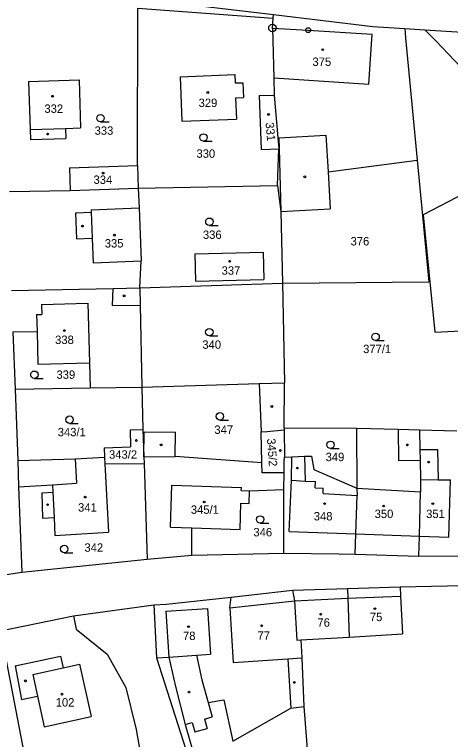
# Model space of a CAD drawing. Extents: x -779596 to -776743, y -1030330 to -1024513.
# Drawn here: x -778185.6 to -778097.2, y -1024857.5 to -1024710.7 of the extents above; entities that cross this region are included whole.
import ezdxf

# ---------------------------------------------------------------- set-up
doc = ezdxf.new("R2010")
doc.units = 0
for name, color, linetype in [('hranice parcel', 7, 'Continuous'), ('hranice vnitřní', 7, 'Continuous'), ('kultura', 7, 'Continuous'), ('Kód', 7, 'Continuous'), ('č_pacel stav_', 7, 'Continuous'), ('č_parcel poz_', 7, 'Continuous')]:
    doc.layers.add(name, color=color, linetype=linetype)

msp = doc.modelspace()

# ---------------------------------------------------------------- linework, layer by layer
at = {"layer": 'hranice parcel'}
for points in [[(-778160.55, -1024707.39), (-778133.07, -1024710.69)], [(-778160.63, -1024741.23), (-778160.55, -1024709.39)], [(-778160.55, -1024709.39), (-778133.13, -1024711.38)], [(-778133.13, -1024711.38), (-778133.07, -1024710.69)], [(-778133.07, -1024710.69), (-778112.97, -1024713.11)], [(-778133.3, -1024713.41), (-778133.13, -1024711.38)], [(-778133.3, -1024713.41), (-778133.03, -1024723.5)], [(-778112.97, -1024713.11), (-778106.49, -1024713.51)], [(-778106.49, -1024713.51), (-778106.32, -1024715.36)], [(-778106.49, -1024713.51), (-778102.38, -1024713.77)], [(-778102.38, -1024713.77), (-778087.35, -1024714.71)], [(-778102.38, -1024713.77), (-778100.2, -1024716.03)], [(-778106.32, -1024715.36), (-778103.98, -1024740.19)], [(-778100.2, -1024716.03), (-778095.04, -1024721.38)], [(-778151.98, -1024723.26), (-778140.93, -1024722.84)], [(-778140.93, -1024722.84), (-778140.87, -1024724.53)], [(-778182.73, -1024724.25), (-778172.49, -1024723.92)], [(-778182.73, -1024724.25), (-778182.41, -1024733.97)], [(-778172.49, -1024723.92), (-778172.17, -1024733.64)], [(-778151.98, -1024723.26), (-778151.64, -1024732.27)], [(-778133.03, -1024723.5), (-778132.93, -1024726.98)], [(-778140.87, -1024724.53), (-778139.26, -1024724.47)], [(-778139.26, -1024724.47), (-778139.15, -1024727.48)], [(-778135.96, -1024727.06), (-778132.93, -1024726.98)], [(-778135.96, -1024727.06), (-778135.57, -1024738)], [(-778132.93, -1024726.98), (-778132.21, -1024735.64)], [(-778140.76, -1024727.54), (-778139.15, -1024727.48)], [(-778140.76, -1024727.54), (-778140.6, -1024731.86)], [(-778151.64, -1024732.27), (-778140.6, -1024731.86)], [(-778182.41, -1024733.97), (-778182.34, -1024735.96)], [(-778175.24, -1024733.74), (-778172.17, -1024733.64)], [(-778175.24, -1024733.74), (-778175.17, -1024735.77)], [(-778182.34, -1024735.96), (-778175.17, -1024735.77)], [(-778132.21, -1024735.64), (-778132.02, -1024737.88)], [(-778135.57, -1024738), (-778132.02, -1024737.88)], [(-778132.26, -1024745.3), (-778132.02, -1024737.88)], [(-778122.03, -1024742.54), (-778103.98, -1024740.19)], [(-778103.98, -1024740.19), (-778101.62, -1024764.81)], [(-778174.43, -1024741.71), (-778160.63, -1024741.23)], [(-778174.43, -1024741.71), (-778174.27, -1024746.3)], [(-778160.63, -1024741.23), (-778160.47, -1024745.82)], [(-778082.6, -1024740.74), (-778102.73, -1024751.23)], [(-778122.03, -1024742.54), (-778121.59, -1024750.05)], [(-778186.58, -1024746.54), (-778174.27, -1024746.3)], [(-778174.27, -1024746.3), (-778160.47, -1024745.82)], [(-778160.47, -1024745.82), (-778132.26, -1024745.3)], [(-778160.47, -1024745.82), (-778160.29, -1024749.84)], [(-778132.26, -1024745.3), (-778131.57, -1024750.56)], [(-778160.29, -1024749.84), (-778159.87, -1024760.58)], [(-778131.57, -1024750.56), (-778121.59, -1024750.05)], [(-778131.57, -1024750.56), (-778131.28, -1024765.07)], [(-778102.73, -1024751.23), (-778100.38, -1024775)], [(-778149, -1024759.12), (-778135.14, -1024758.79)], [(-778149, -1024759.12), (-778148.87, -1024764.68)], [(-778135.14, -1024758.79), (-778135.01, -1024764.35)], [(-778160.16, -1024766.03), (-778159.87, -1024760.58)], [(-778160.16, -1024766.03), (-778131.28, -1024765.07)], [(-778148.87, -1024764.68), (-778135.01, -1024764.35)], [(-778131.28, -1024765.07), (-778101.62, -1024764.81)], [(-778131.28, -1024765.07), (-778130.87, -1024785.26)], [(-778186.2, -1024766.58), (-778165.58, -1024766.14)], [(-778165.58, -1024766.14), (-778160.16, -1024766.03)], [(-778160.16, -1024766.03), (-778160.09, -1024769.5)], [(-778160.09, -1024769.5), (-778159.76, -1024786.14)], [(-778100.38, -1024775), (-778068.42, -1024773.37)], [(-778185.87, -1024774.95), (-778180.98, -1024774.86)], [(-778185.87, -1024774.95), (-778185.42, -1024786.53)], [(-778180.98, -1024774.86), (-778180.8, -1024781.49)], [(-778180.8, -1024781.49), (-778170.38, -1024781.21)], [(-778170.38, -1024781.21), (-778170.24, -1024786.3)], [(-778159.76, -1024786.14), (-778135.98, -1024785.42)], [(-778135.98, -1024785.42), (-778130.87, -1024785.26)], [(-778135.98, -1024785.42), (-778135.58, -1024795.2)], [(-778130.92, -1024794.35), (-778130.87, -1024785.26)], [(-778185.42, -1024786.53), (-778170.24, -1024786.3)], [(-778185.42, -1024786.53), (-778184.91, -1024800.99)], [(-778170.24, -1024786.3), (-778159.76, -1024786.14)], [(-778159.76, -1024786.14), (-778159.57, -1024794.74)], [(-778162.14, -1024794.79), (-778159.57, -1024794.74)], [(-778162.14, -1024794.79), (-778162.06, -1024798.24)], [(-778159.57, -1024794.74), (-778159.33, -1024800.24)], [(-778130.92, -1024794.35), (-778130.92, -1024794.8)], [(-778130.92, -1024794.35), (-778116.26, -1024794.42)], [(-778116.26, -1024794.42), (-778116.17, -1024806.58)], [(-778116.26, -1024794.42), (-778107.83, -1024794.65)], [(-778107.83, -1024794.65), (-778103.48, -1024794.77)], [(-778103.48, -1024794.77), (-778103.42, -1024798.74)], [(-778103.48, -1024794.77), (-778095.94, -1024795)], [(-778159.33, -1024800.24), (-778159.29, -1024795.19)], [(-778159.29, -1024795.19), (-778152.93, -1024795.26)], [(-778152.99, -1024800.2), (-778152.93, -1024795.26)], [(-778135.43, -1024801.46), (-778135.58, -1024795.2)], [(-778130.92, -1024794.8), (-778130.86, -1024800.3)], [(-778167.41, -1024798.41), (-778162.06, -1024798.24)], [(-778167.41, -1024798.41), (-778167.3, -1024800.33)], [(-778103.42, -1024798.74), (-778103.38, -1024800.89)], [(-778184.91, -1024800.99), (-778173.3, -1024800.66)], [(-778173.3, -1024800.66), (-778167.3, -1024800.33)], [(-778167.3, -1024800.33), (-778167.23, -1024801.67)], [(-778159.33, -1024800.24), (-778159.28, -1024801.62)], [(-778135.43, -1024801.46), (-778152.99, -1024800.2)], [(-778130.95, -1024801.32), (-778130.86, -1024800.3)], [(-778130.86, -1024800.3), (-778129.35, -1024800.24)], [(-778129.35, -1024800.24), (-778126.82, -1024800.14)], [(-778126.82, -1024800.14), (-778125.37, -1024800.09)], [(-778125.37, -1024800.09), (-778124.91, -1024802.79)], [(-778184.91, -1024800.99), (-778184.72, -1024806.35)], [(-778167.23, -1024801.67), (-778159.28, -1024801.62)], [(-778167.23, -1024801.67), (-778166.49, -1024815.49)], [(-778159.28, -1024801.62), (-778158.66, -1024820.94)], [(-778135.38, -1024803.47), (-778135.43, -1024801.46)], [(-778130.95, -1024803.45), (-778130.95, -1024801.32)], [(-778103.38, -1024800.89), (-778103.32, -1024804.84)], [(-778130.95, -1024803.45), (-778135.38, -1024803.47)], [(-778130.96, -1024806.88), (-778130.95, -1024803.45)], [(-778124.91, -1024802.79), (-778116.17, -1024806.58)], [(-778103.32, -1024804.84), (-778103.28, -1024807.34)], [(-778184.72, -1024806.35), (-778177.86, -1024805.91)], [(-778184.72, -1024806.35), (-778184.1, -1024823.61)], [(-778177.86, -1024805.91), (-778177.79, -1024807.4)], [(-778180.01, -1024807.51), (-778177.79, -1024807.4)], [(-778180.01, -1024807.51), (-778179.86, -1024812.64)], [(-778138.03, -1024809.68), (-778137.93, -1024807.13)], [(-778137.93, -1024807.13), (-778130.96, -1024806.88)], [(-778130.98, -1024819.72), (-778130.96, -1024806.88)], [(-778116.17, -1024806.58), (-778116.13, -1024808.08)], [(-778103.52, -1024816.29), (-778103.28, -1024807.34)], [(-778116.41, -1024815.83), (-778116.13, -1024808.08)], [(-778139.86, -1024814.97), (-778139.69, -1024809.63)], [(-778139.69, -1024809.63), (-778138.03, -1024809.68)], [(-778179.86, -1024812.64), (-778177.54, -1024812.53)], [(-778177.54, -1024812.53), (-778177.37, -1024816.18)], [(-778149.66, -1024820.13), (-778149.61, -1024814.65)], [(-778149.61, -1024814.65), (-778139.86, -1024814.97)], [(-778177.37, -1024816.18), (-778166.49, -1024815.49)], [(-778116.51, -1024819.97), (-778116.41, -1024815.83)], [(-778103.61, -1024820.37), (-778103.52, -1024816.29)], [(-778149.66, -1024820.13), (-778130.98, -1024819.72)], [(-778130.98, -1024819.72), (-778119.86, -1024819.87)], [(-778184.1, -1024823.61), (-778158.66, -1024820.94)], [(-778158.66, -1024820.94), (-778149.66, -1024820.13)], [(-778119.86, -1024819.87), (-778116.51, -1024819.97)], [(-778116.51, -1024819.97), (-778103.61, -1024820.37)], [(-778103.61, -1024820.37), (-778090.93, -1024820.32)], [(-778193.9, -1024825.06), (-778184.1, -1024823.61)], [(-778129.21, -1024827.27), (-778118.06, -1024826.92)], [(-778118.06, -1024826.92), (-778107.44, -1024826.59)], [(-778118.06, -1024826.92), (-778118, -1024828.86)], [(-778107.44, -1024826.59), (-778091.45, -1024826.23)], [(-778107.44, -1024826.59), (-778107.34, -1024828.45)], [(-778141.64, -1024828.64), (-778129.21, -1024827.27)], [(-778129.21, -1024827.27), (-778128.79, -1024829.43)], [(-778107.34, -1024828.45), (-778106.94, -1024836.07)], [(-778154.81, -1024830.1), (-778141.64, -1024828.64)], [(-778141.94, -1024830.85), (-778141.64, -1024828.64)], [(-778128.79, -1024829.43), (-778128.38, -1024837.37)], [(-778118, -1024828.86), (-778117.77, -1024836.73)], [(-778173.59, -1024832.42), (-778157.31, -1024830.23)], [(-778157.31, -1024830.23), (-778154.81, -1024830.1)], [(-778157.31, -1024830.23), (-778156.76, -1024840.95)], [(-778141.94, -1024830.85), (-778141.22, -1024841.91)], [(-778188.42, -1024835.49), (-778173.59, -1024832.42)], [(-778173.59, -1024832.42), (-778173.06, -1024835.13)], [(-778173.06, -1024835.13), (-778166.78, -1024840.23)], [(-778128.38, -1024837.37), (-778127.54, -1024837.32)], [(-778127.54, -1024837.32), (-778117.77, -1024836.73)], [(-778127.54, -1024837.32), (-778127.37, -1024840.94)], [(-778117.77, -1024836.73), (-778106.94, -1024836.07)], [(-778187.93, -1024838.01), (-778180.36, -1024877.36)], [(-778166.78, -1024840.23), (-778163, -1024846.97)], [(-778185.41, -1024842.59), (-778176.25, -1024840.62)], [(-778176.25, -1024840.62), (-778175.73, -1024842.98)], [(-778156.76, -1024840.95), (-778154.27, -1024840.78)], [(-778156.76, -1024840.95), (-778150.3, -1024861.21)], [(-778154.27, -1024840.78), (-778152.92, -1024846.76)], [(-778141.22, -1024841.91), (-778130.18, -1024841.13)], [(-778130.18, -1024841.13), (-778127.37, -1024840.94)], [(-778127.37, -1024840.94), (-778126.92, -1024850.83)], [(-778185.41, -1024842.59), (-778184.15, -1024849.36)], [(-778175.73, -1024842.98), (-778172.36, -1024842.22)], [(-778172.36, -1024842.22), (-778170.04, -1024852.82)], [(-778163, -1024846.97), (-778160.91, -1024855.45)], [(-778152.92, -1024846.76), (-778150.99, -1024854.44)], [(-778184.15, -1024849.36), (-778180.91, -1024848.68)], [(-778180.91, -1024848.68), (-778179.55, -1024854.91)], [(-778146.31, -1024850.01), (-778143.11, -1024849.44)], [(-778146.31, -1024850.01), (-778145.5, -1024852.91)], [(-778143.11, -1024849.44), (-778141.34, -1024857.84)], [(-778141.34, -1024857.84), (-778129.56, -1024851.15)], [(-778129.56, -1024851.15), (-778126.92, -1024850.83)], [(-778126.92, -1024850.83), (-778125.81, -1024865.47)], [(-778179.55, -1024854.91), (-778170.04, -1024852.82)], [(-778147.06, -1024853.34), (-778145.5, -1024852.91)], [(-778147.06, -1024853.34), (-778146.53, -1024855.24)], [(-778150.99, -1024854.44), (-778149.54, -1024854.03)], [(-778150.99, -1024854.44), (-778145, -1024875.04)], [(-778149.54, -1024854.03), (-778149.01, -1024855.96)], [(-778160.91, -1024855.45), (-778157.79, -1024873.21)], [(-778149.01, -1024855.96), (-778146.53, -1024855.24)]]:
    msp.add_lwpolyline(points, dxfattribs=at)
at = {"layer": 'hranice vnitřní'}
for points in [[(-778133.3, -1024713.41), (-778126.07, -1024713.84)], [(-778126.07, -1024713.84), (-778113.07, -1024714.62)], [(-778113.77, -1024724.78), (-778113.07, -1024714.62)], [(-778133.03, -1024723.5), (-778113.77, -1024724.78)], [(-778182.41, -1024733.97), (-778175.24, -1024733.74)], [(-778132.21, -1024735.64), (-778132.01, -1024735.63)], [(-778132.01, -1024735.63), (-778122.46, -1024735.08)], [(-778132.01, -1024735.63), (-778131.94, -1024737.88)], [(-778122.46, -1024735.08), (-778122.03, -1024742.54)], [(-778131.94, -1024737.88), (-778131.57, -1024750.56)], [(-778173.2, -1024750.85), (-778170.02, -1024750.72)], [(-778170.04, -1024750.22), (-778160.29, -1024749.84)], [(-778170.04, -1024750.22), (-778170.02, -1024750.72)], [(-778170.02, -1024750.72), (-778169.81, -1024755.97)], [(-778173.2, -1024750.85), (-778173, -1024756.1)], [(-778173, -1024756.1), (-778169.81, -1024755.97)], [(-778169.81, -1024755.97), (-778169.61, -1024760.96)], [(-778169.61, -1024760.96), (-778159.87, -1024760.58)], [(-778165.72, -1024769.62), (-778165.58, -1024766.14)], [(-778180.09, -1024769.39), (-778170.71, -1024769.14)], [(-778180.09, -1024769.39), (-778180.03, -1024771.39)], [(-778170.71, -1024769.14), (-778170.38, -1024781.21)], [(-778165.72, -1024769.62), (-778160.09, -1024769.5)], [(-778181.08, -1024771.42), (-778180.03, -1024771.39)], [(-778181.08, -1024771.42), (-778180.98, -1024774.86)], [(-778107.83, -1024794.65), (-778107.73, -1024800.97)], [(-778135.58, -1024795.2), (-778134.38, -1024795.1)], [(-778134.38, -1024795.1), (-778130.92, -1024794.8)], [(-778103.42, -1024798.74), (-778099.87, -1024798.79)], [(-778099.87, -1024798.79), (-778099.71, -1024804.89)], [(-778173.3, -1024800.66), (-778173, -1024805.6)], [(-778159.33, -1024800.24), (-778152.99, -1024800.2)], [(-778129.44, -1024804.99), (-778129.35, -1024800.24)], [(-778126.82, -1024800.14), (-778126.63, -1024805.15)], [(-778107.73, -1024800.97), (-778103.38, -1024800.89)], [(-778129.92, -1024815.34), (-778129.44, -1024804.99)], [(-778129.44, -1024804.99), (-778126.63, -1024805.15)], [(-778103.32, -1024804.84), (-778099.71, -1024804.89)], [(-778099.71, -1024804.89), (-778097.24, -1024804.92)], [(-778097.52, -1024816.51), (-778097.24, -1024804.92)], [(-778177.86, -1024805.91), (-778173, -1024805.6)], [(-778153.96, -1024814.51), (-778153.68, -1024805.96)], [(-778153.68, -1024805.96), (-778139.58, -1024806.42)], [(-778139.61, -1024807.08), (-778139.58, -1024806.42)], [(-778126.63, -1024805.15), (-778124.57, -1024805.27)], [(-778124.64, -1024806.49), (-778124.57, -1024805.27)], [(-778124.64, -1024806.49), (-778122.98, -1024806.58)], [(-778177.79, -1024807.4), (-778177.54, -1024812.53)], [(-778139.61, -1024807.08), (-778137.93, -1024807.13)], [(-778123.04, -1024807.68), (-778122.98, -1024806.58)], [(-778123.04, -1024807.68), (-778116.13, -1024808.08)], [(-778116.17, -1024806.58), (-778103.28, -1024807.34)], [(-778153.96, -1024814.51), (-778149.61, -1024814.65)], [(-778129.92, -1024815.34), (-778116.41, -1024815.83)], [(-778116.41, -1024815.83), (-778103.52, -1024816.29)], [(-778103.52, -1024816.29), (-778097.52, -1024816.51)], [(-778118, -1024828.86), (-778107.34, -1024828.45)], [(-778141.94, -1024830.85), (-778128.79, -1024829.43)], [(-778128.79, -1024829.43), (-778118, -1024828.86)], [(-778154.89, -1024831.5), (-778146.45, -1024830.93)], [(-778146.45, -1024830.93), (-778145.83, -1024840.21)], [(-778154.89, -1024831.5), (-778154.27, -1024840.78)], [(-778148.68, -1024840.41), (-778145.83, -1024840.21)], [(-778154.27, -1024840.78), (-778148.68, -1024840.41)], [(-778148.68, -1024840.41), (-778147.6, -1024845.38)], [(-778130.18, -1024841.13), (-778129.56, -1024851.15)], [(-778181.87, -1024844.31), (-778175.73, -1024842.98)], [(-778181.87, -1024844.31), (-778180.91, -1024848.68)], [(-778147.6, -1024845.38), (-778146.31, -1024850.01)]]:
    msp.add_lwpolyline(points, dxfattribs=at)
at = {"layer": 'kultura'}
for points in [[(-778168.12, -1024732.4), (-778166.37, -1024732.4)], [(-778147.27, -1024736.31), (-778145.52, -1024736.31)], [(-778146.07, -1024753.38), (-778144.32, -1024753.38)], [(-778146.08, -1024775.75), (-778144.33, -1024775.75)], [(-778112.39, -1024776.69), (-778110.64, -1024776.69)], [(-778181.53, -1024784.36), (-778179.78, -1024784.36)], [(-778143.94, -1024792.79), (-778142.19, -1024792.79)], [(-778174.4, -1024793.47), (-778172.65, -1024793.47)], [(-778121.52, -1024798.55), (-778119.77, -1024798.55)], [(-778135.79, -1024813.67), (-778134.04, -1024813.67)], [(-778175.48, -1024819.66), (-778173.73, -1024819.66)]]:
    msp.add_lwpolyline(points, dxfattribs=at)
for centre, radius in [((-778123.11, -1024717.79), 0.175), ((-778177.86, -1024727.21), 0.175), ((-778146.4, -1024726.46), 0.175), ((-778168.12, -1024731.65), 0.75), ((-778134.07, -1024730.9), 0.175), ((-778178.84, -1024734.89), 0.175), ((-778147.27, -1024735.56), 0.75), ((-778167.58, -1024742.79), 0.175), ((-778126.75, -1024743.54), 0.175), ((-778146.07, -1024752.63), 0.75), ((-778171.8, -1024753.51), 0.175), ((-778165.31, -1024755.35), 0.175), ((-778141.96, -1024760.63), 0.175), ((-778163.36, -1024767.64), 0.175), ((-778175.47, -1024774.67), 0.175), ((-778146.08, -1024775), 0.75), ((-778112.39, -1024775.94), 0.75), ((-778181.53, -1024783.61), 0.75), ((-778133.4, -1024790.05), 0.175), ((-778143.94, -1024792.04), 0.75), ((-778174.4, -1024792.72), 0.75), ((-778160.87, -1024796.93), 0.175), ((-778155.84, -1024797.82), 0.175), ((-778121.52, -1024797.8), 0.75), ((-778105.95, -1024797.83), 0.175), ((-778131.69, -1024798.96), 0.175), ((-778101.63, -1024801.31), 0.175), ((-778128.24, -1024802.51), 0.175), ((-778171.26, -1024808.4), 0.175), ((-778147.12, -1024809.4), 0.175), ((-778178.84, -1024809.92), 0.175), ((-778122.72, -1024809.72), 0.175), ((-778110.75, -1024810.2), 0.175), ((-778100.79, -1024809.72), 0.175), ((-778135.79, -1024812.92), 0.75), ((-778175.48, -1024818.91), 0.75), ((-778112.53, -1024830.98), 0.175), ((-778123.53, -1024832.11), 0.175), ((-778135.48, -1024834.46), 0.175), ((-778150.3, -1024834.63), 0.175), ((-778183.34, -1024845.61), 0.175), ((-778128.86, -1024845.92), 0.175), ((-778175.93, -1024848.31), 0.175), ((-778150.21, -1024847.89), 0.175)]:
    msp.add_circle(centre, radius, dxfattribs=at)
at = {"layer": 'Kód'}
for centre, radius in [((-778133.3, -1024713.4), 0.75), ((-778133.3, -1024713.4), 0.032), ((-778126.07, -1024713.84), 0.5), ((-778126.07, -1024713.84), 0.032)]:
    msp.add_circle(centre, radius, dxfattribs=at)

# ---------------------------------------------------------------- texts
at = {"layer": 'č_pacel stav_'}
for s, p in [('375', (-778125.18, -1024721.08)), ('329', (-778148.26, -1024729.4)), ('332', (-778179.5, -1024730.58)), ('334', (-778169.55, -1024744.97)), ('335', (-778167.27, -1024757.85)), ('337', (-778143.6, -1024763.36)), ('338', (-778177.33, -1024777.39)), ('343/2', (-778166.41, -1024800.62)), ('341', (-778172.68, -1024811.34)), ('345/1', (-778149.833, -1024811.78)), ('350', (-778112.59, -1024812.64)), ('351', (-778102.15, -1024812.64)), ('348', (-778124.92, -1024813.12)), ('76', (-778124.18, -1024834.64)), ('75', (-778113.55, -1024833.51)), ('78', (-778151.42, -1024837.34)), ('77', (-778136.31, -1024837.27)), ('102', (-778177.21, -1024850.81))]:
    msp.add_text(s, height=1.7, dxfattribs=at).set_placement(p)
for s, rotation, p in [('331', 275.50219, (-778134.712, -1024732.589)), ('345/2', 274.10218, (-778134.399, -1024796.571))]:
    msp.add_text(s, height=1.7, rotation=rotation, dxfattribs=at).set_placement(p)
at = {"layer": 'č_parcel poz_'}
for s, p in [('333', (-778169.33, -1024735.02)), ('330', (-778148.69, -1024739.68)), ('336', (-778147.38, -1024756.11)), ('376', (-778117.46, -1024757.43)), ('340', (-778147.5, -1024778.36)), ('377/1', (-778114.923, -1024779.24)), ('339', (-778177.06, -1024784.44)), ('343/1', (-778176.8, -1024796.08)), ('347', (-778145.06, -1024795.59)), ('349', (-778122.52, -1024801.11)), ('346', (-778137.15, -1024816.35)), ('342', (-778171.39, -1024819.46))]:
    msp.add_text(s, height=1.7, dxfattribs=at).set_placement(p)

doc.saveas('drawing.dxf')
